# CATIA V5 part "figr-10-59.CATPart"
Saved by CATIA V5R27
Part number: Part1
Bounding box of the stored display mesh (mm): x -322.312 to 0, y -118.205 to 88.531, z 0 to 101.951
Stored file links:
  E:\_Deepak\2016_Deepak\CATIA\CATIA V5-6R2016_Deepak\Resources\Part files\Partfiles\c10_catia_v5_6r2016_prt\figr-10-59.CATPart
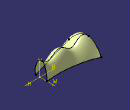
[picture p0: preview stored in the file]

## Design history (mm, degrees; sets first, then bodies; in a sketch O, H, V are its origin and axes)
Set1
  Curve1: Elements (vertex of Sketch2; vertex of Sketch1; vertex of Sketch3)
  Curve2: Elements (Sketch2.P2; vertex of Sketch1; Sketch3.P2)
  Loft1: Sections (Curve2; Sketch4), Guides (Sketch2; Sketch1; Sketch3)
Body1 (main body)
  Sketch1 on zx-plane, origin (0, 0, 0), H (-1, 0, 0), V (0, 0, 1)
    spline S1 through (0, 96.336) (70.1946, 72.4244) (144.1119, 96.336) (203.5098, 63.985) (253.668, 92.1163) (322.3056, 72.4244)
    point P1 (0, 96.336)
    coincidence: P1 V
  Sketch2 on xy-plane, origin (0, 0, 0), H (1, 0, 0), V (0, 1, 0)
    point P1 (0, 47.0553)
    point P2 (-315.9706, 88.5306)
    arc A1 centre (-78.7604, 671.3501) radius 629.2433 from (0, 47.0553) to (-315.9706, 88.5306) cw
    coincidence: P1 V
  Sketch3 on xy-plane, origin (0, 0, 0), H (1, 0, 0), V (0, 1, 0)
    line L1 (0, -26.5991) -> (-311.8959, -118.2048)
    point P1 (0, -26.5991)
    point P2 (-311.8959, -118.2048)
    coincidence: P1 V
  Sketch4 on yz-plane, origin (0, 0, 0), H (0, 1, 0), V (0, 0, 1)
    point P1 (-26.5991, 0)
    point P2 (0, 58.544)
    point P3 (47.0553, 0)
    reference projected point E1 (47.0553, 0) from vertex of Sketch2
    reference projected point E2 (-26.5991, 0) from vertex of Sketch3
    spline S1 through (-26.5991, 0) (-29.9268, 35.6209) (0, 96.336) (47.0553, 0)
    reference projected point E3 (0, 96.336) from vertex of Sketch1
    point P4 (-26.5991, 0)
    point P5 (0, 96.336)
    point P6 (47.0553, 0)
    coincidence: P1 H, P3 H, E1 P3, P1 E2, P4 P1, P5 V, P6 P3, E3 S1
